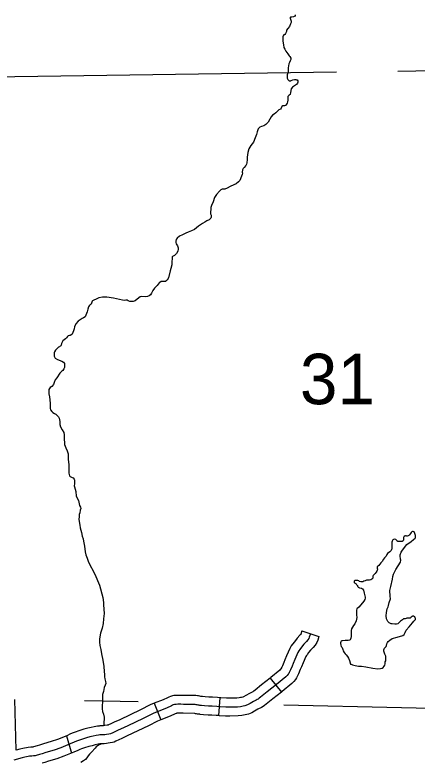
# Model space of a CAD drawing. Extents: x 1720274 to 1751788, y 372074 to 391887.
# Drawn here: x 1730930 to 1731462, y 377014 to 378002 of the extents above; entities that cross this region are included whole.
import ezdxf

# ---------------------------------------------------------------- set-up
doc = ezdxf.new("R2010")
doc.units = 0
for name, color, linetype in [('Level 32', 7, 'Continuous'), ('Level 35', 7, 'Continuous'), ('Level 4', 7, 'Continuous'), ('Level 5', 7, 'Continuous')]:
    doc.layers.add(name, color=color, linetype=linetype)

msp = doc.modelspace()

# ---------------------------------------------------------------- linework, layer by layer
at = {"layer": 'Level 32'}
for p, q in [((1731309.44, 377187.64), (1731331.93, 377180.16)), ((1731267.65, 377125.35), (1731282.3, 377106.72)), ((1731114.54, 377092.11), (1731123.26, 377070.07)), ((1731201.26, 377099.36), (1731199.26, 377075.74)), ((1730998.57, 377049.12), (1731005.35, 377026.28))]:
    msp.add_line(p, q, dxfattribs=at)
for points in [[(1731309.44, 377187.64), (1731308.03, 377183.41), (1731307.9, 377183.06), (1731306.91, 377181.91), (1731303.11, 377178.12), (1731299.52, 377173.41), (1731297.17, 377170.35), (1731295.43, 377167.89), (1731293.61, 377164.69), (1731289.08, 377154.71), (1731287.06, 377149.34), (1731285.5, 377145.86), (1731283.7, 377141.45), (1731282.74, 377139.73), (1731281.83, 377137.67), (1731281.33, 377137.09), (1731280.13, 377135.88), (1731268.5, 377126.02), (1731267.65, 377125.35)], [(1731331.93, 377180.16), (1731330.38, 377175.5), (1731329.25, 377172.49), (1731327.09, 377169.03), (1731324.31, 377165.78), (1731320.98, 377162.47), (1731318.34, 377159), (1731316.24, 377156.28), (1731315.46, 377155.17), (1731314.76, 377153.92), (1731310.99, 377145.64), (1731308.99, 377140.32), (1731307.29, 377136.52), (1731305.09, 377131.14), (1731303.98, 377129.15), (1731303.27, 377127.54), (1731302.29, 377125.58), (1731300.88, 377123.47), (1731298.71, 377120.95), (1731296.2, 377118.44), (1731283.5, 377107.66), (1731282.3, 377106.72)], [(1731320.69, 377183.9), (1731319.2, 377179.45), (1731318.57, 377177.76), (1731317.51, 377176.07), (1731315.61, 377173.84)], [(1731315.61, 377173.84), (1731312.05, 377170.29), (1731308.93, 377166.21), (1731306.71, 377163.31), (1731305.45, 377161.53), (1731304.19, 377159.3), (1731300.03, 377150.17), (1731298.03, 377144.83), (1731296.4, 377141.19), (1731294.39, 377136.29), (1731293.36, 377134.44), (1731292.54, 377132.58), (1731292.02, 377131.54), (1731291.43, 377130.65), (1731290.02, 377129.02), (1731288.16, 377127.16), (1731276, 377116.84), (1731263.54, 377107.04), (1731254.86, 377100.14), (1731253.01, 377098.73), (1731251.67, 377097.69), (1731250.26, 377096.87), (1731249.15, 377096.28), (1731248.04, 377095.76), (1731245.74, 377094.64), (1731241.07, 377091.97), (1731237.73, 377090.19), (1731236.4, 377089.52), (1731235.28, 377089.08), (1731234.1, 377088.78), (1731231.95, 377088.26), (1731230.31, 377087.96), (1731228.24, 377087.59), (1731224.45, 377087.15), (1731214.07, 377086.78), (1731209.18, 377086.92), (1731201.54, 377087.44), (1731197.16, 377087.81), (1731191, 377088.26), (1731186.18, 377088.34), (1731180.79, 377088.72), (1731176.66, 377089.18), (1731175.61, 377089.31), (1731174.64, 377089.35), (1731173.93, 377089.48), (1731172.49, 377089.81), (1731171.02, 377090.07), (1731169.88, 377090.24), (1731168.62, 377090.4), (1731152.91, 377090.66), (1731149.54, 377090.7), (1731145.5, 377090.74), (1731143.27, 377090.66), (1731142.18, 377090.53), (1731141.25, 377090.32), (1731139.61, 377089.9), (1731138.6, 377089.48), (1731137.12, 377088.76), (1731130.74, 377085.77), (1731113.81, 377079.07), (1731101.45, 377072.93), (1731087.82, 377066.3), (1731073.89, 377059.6), (1731066.64, 377056.37), (1731062.47, 377054.4), (1731059, 377052.67), (1731057.58, 377052.12), (1731056.48, 377051.8), (1731054.28, 377051.41), (1731051.44, 377051.01), (1731049.39, 377050.54), (1731047.35, 377050.38), (1731044.2, 377050.22), (1731042.78, 377050.22), (1731040.89, 377050.15), (1731037.58, 377049.44), (1731033.64, 377048.49), (1731029.55, 377047.54), (1731024.77, 377046.35), (1731018.43, 377044.38), (1731014.24, 377042.85), (1731011.83, 377041.97), (1731008.66, 377040.7), (1731003.52, 377038.35), (1730991.02, 377033.2), (1730982.08, 377030.09), (1730971.48, 377026.98), (1730966.28, 377025.33), (1730962.86, 377024.31), (1730961.4, 377023.93), (1730959.87, 377023.42), (1730957.21, 377022.79), (1730955.12, 377022.47), (1730952.64, 377022.35), (1730949.85, 377022.03), (1730948.01, 377021.65), (1730945.66, 377021.2), (1730943.57, 377020.69), (1730940.15, 377019.81), (1730929.04, 377016.88)], [(1731267.65, 377125.35), (1731256.19, 377116.34), (1731247.59, 377109.49), (1731245.78, 377108.12), (1731245.03, 377107.54), (1731244.5, 377107.23), (1731243.85, 377106.88), (1731242.95, 377106.46), (1731240.21, 377105.13), (1731235.33, 377102.34), (1731232.29, 377100.72), (1731231.59, 377100.37), (1731231.27, 377100.29), (1731229.49, 377099.86), (1731228.21, 377099.62), (1731226.5, 377099.32), (1731223.55, 377098.97), (1731214.04, 377098.63), (1731209.76, 377098.76), (1731202.44, 377099.26), (1731201.26, 377099.36)], [(1731201.26, 377099.36), (1731198.09, 377099.63), (1731191.53, 377100.1), (1731186.69, 377100.18), (1731181.87, 377100.52), (1731178.03, 377100.95), (1731176.58, 377101.13), (1731176.05, 377101.15), (1731174.86, 377101.43), (1731172.89, 377101.77), (1731171.54, 377101.97), (1731169.5, 377102.24), (1731153.08, 377102.51), (1731149.68, 377102.55), (1731145.34, 377102.59), (1731142.37, 377102.48), (1731140.18, 377102.23), (1731138.46, 377101.84), (1731135.83, 377101.16), (1731133.72, 377100.28), (1731132.02, 377099.46), (1731126.05, 377096.66), (1731114.54, 377092.11)], [(1731282.3, 377106.72), (1731270.89, 377097.75), (1731262.14, 377090.78), (1731260.24, 377089.34), (1731258.32, 377087.84), (1731256.03, 377086.52), (1731254.45, 377085.68), (1731253.13, 377085.06), (1731251.27, 377084.16), (1731246.8, 377081.6), (1731243.17, 377079.66), (1731241.26, 377078.7), (1731238.94, 377077.78), (1731236.93, 377077.27), (1731234.4, 377076.66), (1731232.42, 377076.3), (1731229.97, 377075.86), (1731225.36, 377075.32), (1731214.1, 377074.92), (1731208.59, 377075.09), (1731200.63, 377075.63), (1731199.25, 377075.74)], [(1730932.2, 377029.97), (1730930.49, 377097.21)], [(1731114.54, 377092.11), (1731108.99, 377089.91), (1731096.22, 377083.56), (1731082.67, 377076.97), (1731068.9, 377070.36), (1731061.7, 377067.14), (1731057.29, 377065.06), (1731054.19, 377063.51), (1731053.8, 377063.36), (1731052.42, 377063.11), (1731049.29, 377062.68), (1731047.6, 377062.29), (1731046.6, 377062.21), (1731043.9, 377062.07), (1731042.53, 377062.07), (1731041.68, 377062.04)], [(1731199.25, 377075.74), (1731196.23, 377076), (1731190.48, 377076.42), (1731185.67, 377076.5), (1731179.71, 377076.91), (1731175.29, 377077.41), (1731174.64, 377077.49), (1731173.35, 377077.55), (1731171.53, 377077.87), (1731170.13, 377078.2), (1731169.15, 377078.36), (1731168.23, 377078.5), (1731167.74, 377078.57), (1731152.74, 377078.81), (1731149.41, 377078.85), (1731145.66, 377078.89), (1731144.18, 377078.83), (1731144.04, 377078.8), (1731143.41, 377078.64), (1731142.23, 377078.06), (1731135.44, 377074.89), (1731123.26, 377070.07)], [(1731041.67, 377062.04), (1731039.39, 377061.94), (1731034.96, 377060.99), (1731030.93, 377060.02), (1731026.78, 377059.07), (1731021.57, 377057.76), (1731014.64, 377055.61), (1731010.16, 377053.98), (1731007.58, 377053.03), (1731003.99, 377051.59), (1730998.8, 377049.22), (1730986.82, 377044.29), (1730978.46, 377041.38), (1730968.02, 377038.31), (1730962.8, 377036.66), (1730959.69, 377035.73)], [(1731123.26, 377070.07), (1731118.64, 377068.24), (1731106.68, 377062.29), (1731092.98, 377055.64), (1731078.87, 377048.85), (1731071.58, 377045.6), (1731067.65, 377043.74), (1731063.81, 377041.82), (1731061.37, 377040.87), (1731059.16, 377040.24), (1731056.14, 377039.7), (1731053.6, 377039.35), (1731051.19, 377038.79), (1731048.1, 377038.56), (1731044.49, 377038.37), (1731043.03, 377038.37), (1731042.66, 377038.36)], [(1730959.69, 377035.73), (1730959.67, 377035.73), (1730958.02, 377035.3), (1730956.62, 377034.83), (1730954.94, 377034.43), (1730953.92, 377034.28), (1730951.67, 377034.16), (1730947.98, 377033.74), (1730945.71, 377033.27), (1730943.16, 377032.79), (1730940.69, 377032.19), (1730937.15, 377031.27), (1730932.2, 377029.97)], [(1731042.66, 377038.36), (1731042.39, 377038.35), (1731040.21, 377037.88), (1731036.36, 377036.96), (1731032.32, 377036.02), (1731027.97, 377034.93), (1731022.21, 377033.15), (1731018.32, 377031.73), (1731016.08, 377030.9), (1731013.33, 377029.8), (1731008.24, 377027.48), (1730995.23, 377022.12), (1730985.7, 377018.8), (1730974.95, 377015.65), (1730969.76, 377014), (1730966.42, 377013.01)]]:
    msp.add_lwpolyline(points, dxfattribs=at)
at = {"layer": 'Level 35'}
for points in [[(1731300.38, 378002.16), (1731300.38, 378001.15), (1731300.38, 378000.37), (1731299.37, 377999.7), (1731298.36, 377999.36), (1731296.23, 377999.13), (1731294.55, 377999.02), (1731294.1, 377998.35), (1731293.99, 377997.68), (1731295.23, 377993.53), (1731295.23, 377991.84), (1731294.33, 377990.27), (1731292.98, 377986.57), (1731290.97, 377983.99), (1731289.17, 377981.86), (1731288.95, 377979.84), (1731287.83, 377977.49), (1731286.82, 377976.25), (1731285.7, 377975.47), (1731284.69, 377974.46), (1731284.13, 377973.11), (1731284.13, 377971.09), (1731284.13, 377967.39), (1731285.14, 377962.23), (1731285.59, 377959.09), (1731286.82, 377956.51), (1731288.05, 377954.15), (1731289.51, 377952.13), (1731290.85, 377950.45), (1731291.64, 377949.1), (1731292.76, 377947.98), (1731293.66, 377947.09), (1731294.78, 377944.73), (1731294.66, 377943.16), (1731293.99, 377941.25), (1731292.98, 377939.23), (1731292.09, 377937.1), (1731291.3, 377931.83), (1731291.3, 377926.44), (1731290.07, 377922.74), (1731289.96, 377920.16), (1731290.07, 377918.26), (1731290.85, 377916.8), (1731291.64, 377915.68), (1731292.76, 377914.67), (1731293.66, 377914.67), (1731294.78, 377915), (1731295.45, 377915.45), (1731297.47, 377916.12), (1731299.71, 377916.57), (1731301.61, 377916.69), (1731302.4, 377916.35), (1731303.07, 377916.01), (1731304.19, 377914.89), (1731304.3, 377913.99), (1731304.3, 377913.1), (1731303.85, 377911.75), (1731302.51, 377910.18), (1731299.6, 377908.38), (1731297.13, 377906.37), (1731295.34, 377904.46), (1731294.22, 377899.19), (1731293.88, 377896.83), (1731292.76, 377895.82)], [(1731292.76, 377895.82), (1731291.08, 377894.25), (1731290.74, 377892.9), (1731290.74, 377891.22), (1731290.74, 377889.31), (1731290.52, 377887.18), (1731290.07, 377885.16), (1731289.29, 377883.93), (1731287.83, 377882.36), (1731286.6, 377881.8), (1731284.24, 377881.69), (1731282.9, 377880.79), (1731281.89, 377878.66), (1731281.11, 377877.54), (1731278.98, 377876.3), (1731277.18, 377874.73), (1731275.05, 377872.6), (1731272.7, 377870.58), (1731270.46, 377869.35), (1731268.78, 377867.22), (1731267.21, 377864.3), (1731264.86, 377860.37), (1731261.72, 377856.9), (1731259.03, 377855.33), (1731255.89, 377854.54), (1731253.76, 377853.53), (1731251.74, 377851.4), (1731250.18, 377847.25), (1731249.39, 377844), (1731247.6, 377839.51), (1731245.47, 377833.79), (1731242, 377829.19), (1731239.19, 377824.93), (1731237.85, 377820.21), (1731237.63, 377816.96), (1731237.18, 377813.71), (1731237.18, 377810.9), (1731236.95, 377806.64), (1731236.28, 377804.62), (1731235.27, 377802.71), (1731233.03, 377800.25), (1731231.8, 377798.9), (1731231.13, 377797.33), (1731230.68, 377794.3), (1731230.9, 377792.73), (1731230.68, 377791.16), (1731229.89, 377788.8), (1731227.43, 377783.2), (1731225.52, 377781.29), (1731222.72, 377778.71), (1731219.47, 377777.36), (1731214.88, 377775.12), (1731210.62, 377772.88), (1731207.59, 377771.75), (1731204.23, 377771.64), (1731202.33, 377770.74), (1731200.53, 377768.84), (1731196.5, 377764.58), (1731193.92, 377760.65), (1731192.13, 377754.93), (1731190, 377749.99), (1731189.33, 377747.52), (1731188.65, 377739.22), (1731189.44, 377737.43), (1731189.44, 377736.42), (1731189.44, 377734.62), (1731188.99, 377733.28), (1731187.98, 377731.82), (1731187.08, 377731.03), (1731184.06, 377729.69), (1731181.48, 377728.12), (1731178.01, 377726.21), (1731172.96, 377722.51), (1731167.7, 377718.25), (1731163.55, 377716.45), (1731159.18, 377714.88), (1731156.38, 377713.53), (1731151.9, 377711.4), (1731147.75, 377709.38), (1731144.61, 377706.92), (1731143.27, 377704.9), (1731143.04, 377702.88), (1731142.93, 377701.31), (1731143.49, 377699.18), (1731145.06, 377696.71), (1731146.07, 377694.02), (1731145.96, 377692.22), (1731145.62, 377689.53), (1731143.94, 377686.39), (1731141.03, 377683.92), (1731138.67, 377682.8), (1731138, 377682.01), (1731138, 377680.33), (1731138, 377678.65), (1731137.89, 377676.85), (1731137.66, 377675.73), (1731137.55, 377671.69), (1731136.54, 377666.76), (1731135.31, 377663.5), (1731133.29, 377654.64), (1731131.73, 377651.16)], [(1731131.73, 377651.16), (1731130.27, 377650.27), (1731129.15, 377649.71), (1731128.25, 377649.71), (1731126.68, 377649.59), (1731125.23, 377649.59), (1731123.43, 377649.48), (1731121.75, 377648.47), (1731120.86, 377647.69), (1731118.5, 377644.43), (1731114.92, 377640.62), (1731112.45, 377637.82), (1731110.88, 377634.11), (1731109.54, 377632.09), (1731107.74, 377630.52), (1731105.5, 377629.74), (1731103.04, 377629.29), (1731097.77, 377629.74), (1731095.87, 377629.18), (1731091.83, 377626.04), (1731089.25, 377624.02), (1731086.45, 377623.35), (1731083.76, 377623.23), (1731082.08, 377623.35), (1731080.06, 377624.24), (1731078.72, 377624.92), (1731076.81, 377624.92), (1731074.8, 377624.69), (1731072.44, 377624.92), (1731068.52, 377625.93), (1731060.68, 377627.72), (1731052.05, 377628.73), (1731046, 377628.95), (1731041.07, 377628.06), (1731038.83, 377626.49), (1731037.03, 377625.81), (1731035.46, 377625.25), (1731034.45, 377625.03), (1731033.11, 377624.24), (1731032.44, 377623.46), (1731031.43, 377621.1), (1731030.98, 377619.64), (1731029.97, 377618.63), (1731028.63, 377617.62), (1731027.84, 377616.17), (1731026.95, 377613.14), (1731025.71, 377609.66), (1731024.82, 377607.42), (1731024.15, 377605.06), (1731023.14, 377602.7), (1731021.12, 377601.47), (1731019.1, 377600.46), (1731013.95, 377596.98), (1731010.92, 377593.84), (1731009.02, 377589.69), (1731008.79, 377587.22), (1731008.01, 377584.42), (1731005.88, 377580.16), (1731004.42, 377578.81), (1731003.53, 377578.36), (1731002.4, 377578.14), (1731000.61, 377577.8), (1730999.94, 377576.9), (1730998.71, 377575.33), (1730997.03, 377573.88), (1730993.78, 377571.07), (1730992.66, 377569.61), (1730992.1, 377567.59), (1730991.42, 377565.57), (1730991.09, 377564.45), (1730990.41, 377563.89), (1730989.18, 377563.11), (1730987.84, 377562.66), (1730986.16, 377561.09), (1730984.14, 377558.62), (1730982.91, 377556.82), (1730982.23, 377555.59), (1730982.12, 377554.69), (1730982.12, 377552.9), (1730982.46, 377550.77), (1730983.8, 377548.19), (1730986.83, 377546.28), (1730992.21, 377544.26), (1730994.78, 377542.8), (1730996.02, 377541.23), (1730996.13, 377538.88), (1730996.02, 377535.96), (1730995.23, 377534.16), (1730993.55, 377532.15), (1730992.21, 377531.25), (1730989.63, 377528.44), (1730985.6, 377522.39), (1730983.69, 377519.81), (1730982.46, 377516.1), (1730981.45, 377513.41), (1730978.98, 377510.94), (1730977.19, 377509.26), (1730975.29, 377506.79), (1730975.06, 377505.56), (1730975.06, 377504.33), (1730975.06, 377501.19)], [(1730975.06, 377501.19), (1730976.18, 377497.15), (1730976.85, 377488.96), (1730977.19, 377484.13), (1730977.19, 377481.78), (1730977.64, 377480.1), (1730979.21, 377477.74), (1730980.55, 377476.51), (1730982.79, 377474.94), (1730984.47, 377474.04), (1730987.84, 377470.9), (1730988.73, 377468.77), (1730989.85, 377464.39), (1730989.63, 377460.58), (1730990.64, 377457.66), (1730992.99, 377453.73), (1730994.9, 377449.92), (1730995.68, 377446.78), (1730995.68, 377443.53), (1730996.13, 377433.99), (1730997.7, 377429.95), (1730999.38, 377425.91), (1731000.95, 377421.65), (1731000.95, 377420.31), (1731000.95, 377417.73), (1731000.72, 377414.59), (1731001.73, 377407.41), (1731001.51, 377402.69), (1731001.51, 377399.22), (1731001.84, 377396.3), (1731002.07, 377394.39), (1731002.74, 377392.82), (1731003.41, 377391.81), (1731004.2, 377391.36), (1731006.22, 377390.69), (1731007.22, 377390.02), (1731008.68, 377388.34), (1731009.02, 377387.21), (1731009.02, 377385.98), (1731009.02, 377383.85), (1731009.02, 377381.94), (1731008.9, 377379.59), (1731009.13, 377378.24), (1731010.81, 377372.18), (1731011.15, 377365.68), (1731014.51, 377360.07), (1731015.74, 377353.67), (1731017.2, 377351.09), (1731017.42, 377349.52), (1731016.75, 377347.28), (1731015.96, 377343.8), (1731015.29, 377341.67), (1731015.18, 377338.75), (1731015.07, 377335.16), (1731016.08, 377327.54), (1731016.64, 377323.83), (1731018.21, 377317.78), (1731019.44, 377313.18), (1731020.45, 377309.48), (1731021.01, 377306.56), (1731022.24, 377299.94), (1731023.25, 377292.31), (1731024.15, 377288.39), (1731025.83, 377283.68), (1731027.84, 377278.74), (1731035.8, 377262.81), (1731041.96, 377248.23), (1731046.56, 377232.07), (1731047.57, 377225.23), (1731047.57, 377222.09), (1731048.46, 377210.65), (1731047.57, 377203.81), (1731046.78, 377197.64), (1731045.55, 377191.36), (1731043.31, 377184.62), (1731042.19, 377177.33), (1731042.19, 377172.96), (1731042.52, 377168.25), (1731043.76, 377163.31), (1731044.99, 377157.37), (1731046.56, 377149.07), (1731047.68, 377140.54), (1731048.24, 377134.26), (1731048.57, 377130), (1731048.91, 377127.08), (1731049.25, 377124.39), (1731050.03, 377121.02), (1731050.59, 377118.1), (1731049.81, 377116.2), (1731048.24, 377112.83), (1731047.79, 377110.48), (1731047.34, 377107.67), (1731046.22, 377103.75), (1731046.22, 377100.04), (1731046.22, 377094.55), (1731045.66, 377088.15), (1731045.66, 377084.9), (1731046.33, 377081.09), (1731047.57, 377077.61), (1731048.35, 377073.8), (1731048.35, 377070.88)], [(1731458.93, 377310.14), (1731459.38, 377311.39), (1731459.38, 377312.52), (1731459.38, 377313.98), (1731459.16, 377315.11), (1731458.82, 377316.36), (1731458.25, 377317.82), (1731457.8, 377318.5), (1731457.24, 377318.84), (1731456.56, 377318.95), (1731455.55, 377318.95), (1731454.76, 377318.73), (1731453.97, 377317.94), (1731452.84, 377316.36), (1731451.48, 377314.77), (1731450.69, 377313.98), (1731449.9, 377313.42), (1731448.55, 377312.97), (1731448.21, 377312.97), (1731447.08, 377313.31), (1731446.41, 377313.31), (1731445.28, 377313.19), (1731444.49, 377312.97), (1731444.04, 377312.29), (1731443.81, 377311.27), (1731443.81, 377310.71), (1731443.81, 377309.35), (1731443.81, 377308.45), (1731443.59, 377307.66), (1731443.02, 377306.76), (1731441.78, 377305.97), (1731440.77, 377305.85), (1731439.86, 377305.85), (1731438.28, 377305.85), (1731436.14, 377305.97), (1731434.9, 377306.98), (1731434.34, 377307.77), (1731433.32, 377308.45), (1731431.4, 377308.79), (1731430.27, 377308.68), (1731429.71, 377308.23), (1731429.15, 377307.21), (1731428.58, 377306.19), (1731428.36, 377304.84), (1731428.13, 377300.77), (1731428.36, 377296.37), (1731427.91, 377295.13), (1731427.45, 377293.89), (1731425.65, 377292.19), (1731422.49, 377290.16), (1731421.7, 377288.69), (1731420.57, 377286.55), (1731418.77, 377284.4), (1731417.08, 377282.48), (1731415.27, 377279.66), (1731413.92, 377277.85), (1731410.87, 377274.13), (1731409.06, 377272.43), (1731408.73, 377271.19), (1731408.73, 377270.74), (1731409.18, 377269.5), (1731409.18, 377268.93), (1731409.06, 377268.25), (1731408.5, 377266.79), (1731407.49, 377265.32), (1731406.13, 377263.63), (1731404.89, 377262.38), (1731403.42, 377261.03), (1731403.2, 377259.9), (1731403.2, 377258.43), (1731403.2, 377257.53), (1731402.63, 377256.85), (1731401.73, 377255.95), (1731400.38, 377255.04), (1731398.69, 377254.71), (1731396.65, 377254.71), (1731394.85, 377254.71), (1731393.04, 377254.14), (1731391.47, 377253.35), (1731389.77, 377252.79), (1731387.29, 377252.79), (1731385.49, 377253.01), (1731384.47, 377253.8), (1731383.23, 377254.25), (1731381.31, 377254.37), (1731379.39, 377254.37), (1731378.38, 377253.58), (1731378.27, 377252.33), (1731378.38, 377251.88), (1731379.06, 377251.09), (1731380.52, 377250.19), (1731381.31, 377249.74), (1731382.21, 377248.61), (1731382.67, 377247.71), (1731383.12, 377246.35), (1731383.79, 377245.67), (1731385.6, 377244.54), (1731388.31, 377244.09), (1731389.43, 377243.3), (1731390.79, 377241.38), (1731391.58, 377237.77)], [(1731376.46, 377143.04), (1731379.94, 377142.1), (1731384.38, 377141.28), (1731388.14, 377140.98), (1731394, 377140.22), (1731403.17, 377138.42), (1731409.63, 377137.67), (1731413.09, 377138.12), (1731415.34, 377138.57), (1731417, 377139.47), (1731418.05, 377140.98), (1731418.8, 377142.48), (1731419.25, 377144.13), (1731419.4, 377145.19), (1731419.4, 377146.99), (1731420.45, 377148.35), (1731420.45, 377149.4), (1731420.45, 377150.75), (1731420.45, 377151.81), (1731420.15, 377154.51), (1731418.8, 377157.22), (1731417.9, 377159.48), (1731417.6, 377160.98), (1731417.6, 377162.94), (1731418.35, 377164.74), (1731418.35, 377164.74), (1731420.61, 377167.15), (1731421.21, 377168.65), (1731421.66, 377170.61), (1731422.56, 377172.26), (1731423.46, 377173.77), (1731425.41, 377175.72), (1731428.72, 377177.68), (1731435.48, 377179.63), (1731442.55, 377181.59), (1731444.65, 377182.94), (1731444.8, 377183.7), (1731445.71, 377185.5), (1731447.06, 377188.66), (1731451.27, 377193.32), (1731455.32, 377198.59), (1731457.28, 377200.69), (1731458.93, 377202.2), (1731459.38, 377202.95), (1731459.38, 377204), (1731459.23, 377204.91), (1731458.93, 377205.81), (1731458.18, 377206.56), (1731456.98, 377207.16), (1731455.47, 377207.16), (1731454.87, 377206.71), (1731453.97, 377205.81), (1731453.37, 377205.36), (1731452.62, 377204.76), (1731451.27, 377204.61), (1731450.21, 377204.76), (1731449.01, 377204.76), (1731448.11, 377204.46), (1731447.21, 377204.15), (1731445.94, 377203.85), (1731444.88, 377203.68), (1731443.63, 377203.5), (1731442.29, 377202.52), (1731439.89, 377200.47), (1731435.97, 377197.26), (1731434.55, 377196.64), (1731433.84, 377196.64), (1731432.15, 377196.64), (1731428.76, 377196.91), (1731427.16, 377197.26), (1731424.85, 377198.51), (1731422.89, 377200.29), (1731421.91, 377201.81), (1731421.11, 377203.59), (1731420.93, 377207.77), (1731421.2, 377211.96), (1731422.18, 377217.04), (1731423.42, 377219.62), (1731423.78, 377221.41), (1731424.85, 377225.42), (1731426.45, 377229.96), (1731426.09, 377233.61), (1731425.56, 377241.1), (1731426.89, 377246.62), (1731429.12, 377255.97), (1731429.57, 377259.54), (1731430.46, 377262.66), (1731433.48, 377268.8), (1731439.89, 377278.51), (1731440.25, 377281.36), (1731439.89, 377282.43), (1731439.54, 377283.95), (1731439.27, 377285.73), (1731439.27, 377286.8), (1731439.27, 377288.49), (1731440.43, 377291.61), (1731442.38, 377294.55), (1731447.9, 377301.86), (1731453.78, 377305.95), (1731456.9, 377308.45), (1731458.93, 377310.14)], [(1731391.58, 377237.77), (1731393.16, 377232.35), (1731393.16, 377230.99), (1731392.48, 377229.41), (1731391.24, 377227.16), (1731389.32, 377224.78), (1731384.81, 377219.25), (1731382.1, 377216.88), (1731381.42, 377215.07), (1731381.42, 377212.48), (1731381.42, 377209.2), (1731381.88, 377205.36), (1731380.97, 377200.96), (1731379.51, 377197.01), (1731377.7, 377194.98), (1731374.99, 377190.46), (1731374.66, 377188.31), (1731374.54, 377184.47), (1731374.54, 377180.3), (1731374.09, 377178.15), (1731373.75, 377176.8), (1731373.19, 377176.01), (1731372.4, 377175.55), (1731370.48, 377174.99), (1731366.53, 377174.88), (1731363.04, 377174.65), (1731362.02, 377174.54), (1731361.23, 377174.09), (1731360.78, 377173.41), (1731360.55, 377171.83), (1731360.55, 377170.93), (1731360.89, 377169.01), (1731361.46, 377167.31), (1731362.58, 377165.62), (1731363.6, 377163.25), (1731364.16, 377161.22), (1731365.29, 377159.41), (1731366.42, 377157.26), (1731367.89, 377156.13), (1731369.8, 377153.99), (1731371.05, 377151.84), (1731372.29, 377148.79), (1731373.19, 377145.63), (1731373.41, 377144.62), (1731373.84, 377143.97), (1731374.43, 377143.6), (1731375.22, 377143.38), (1731376.46, 377143.04)], [(1731048.35, 377070.88), (1731047.9, 377066.95), (1731047.9, 377063.56)], [(1731044.05, 377038.04), (1731043.76, 377037.9), (1731040.95, 377036.67), (1731037.82, 377034.65), (1731036.36, 377032.85), (1731031.77, 377027.47), (1731028.85, 377024.77), (1731027.06, 377022.64), (1731025.6, 377020.06), (1731023.58, 377017.82), (1731021.01, 377016.14), (1731017.31, 377013.67)]]:
    msp.add_lwpolyline(points, dxfattribs=at)
at = {"layer": 'Level 4'}
for points in [[(1731022.18, 377095.93), (1731093.23, 377094.35)], [(1731285.69, 377090.06), (1731751.61, 377079.67), (1731776.02, 377079.14)]]:
    msp.add_lwpolyline(points, dxfattribs=at)
at = {"layer": 'Level 5'}
for points in [[(1730899.73, 377920.32), (1731355.23, 377926.61)], [(1731436.02, 377927.72), (1731507.25, 377928.71)]]:
    msp.add_lwpolyline(points, dxfattribs=at)

# ---------------------------------------------------------------- texts
msp.add_text('31', height=66.739, dxfattribs=at).set_placement((1731306.82, 377487.37))

doc.saveas('drawing.dxf')
